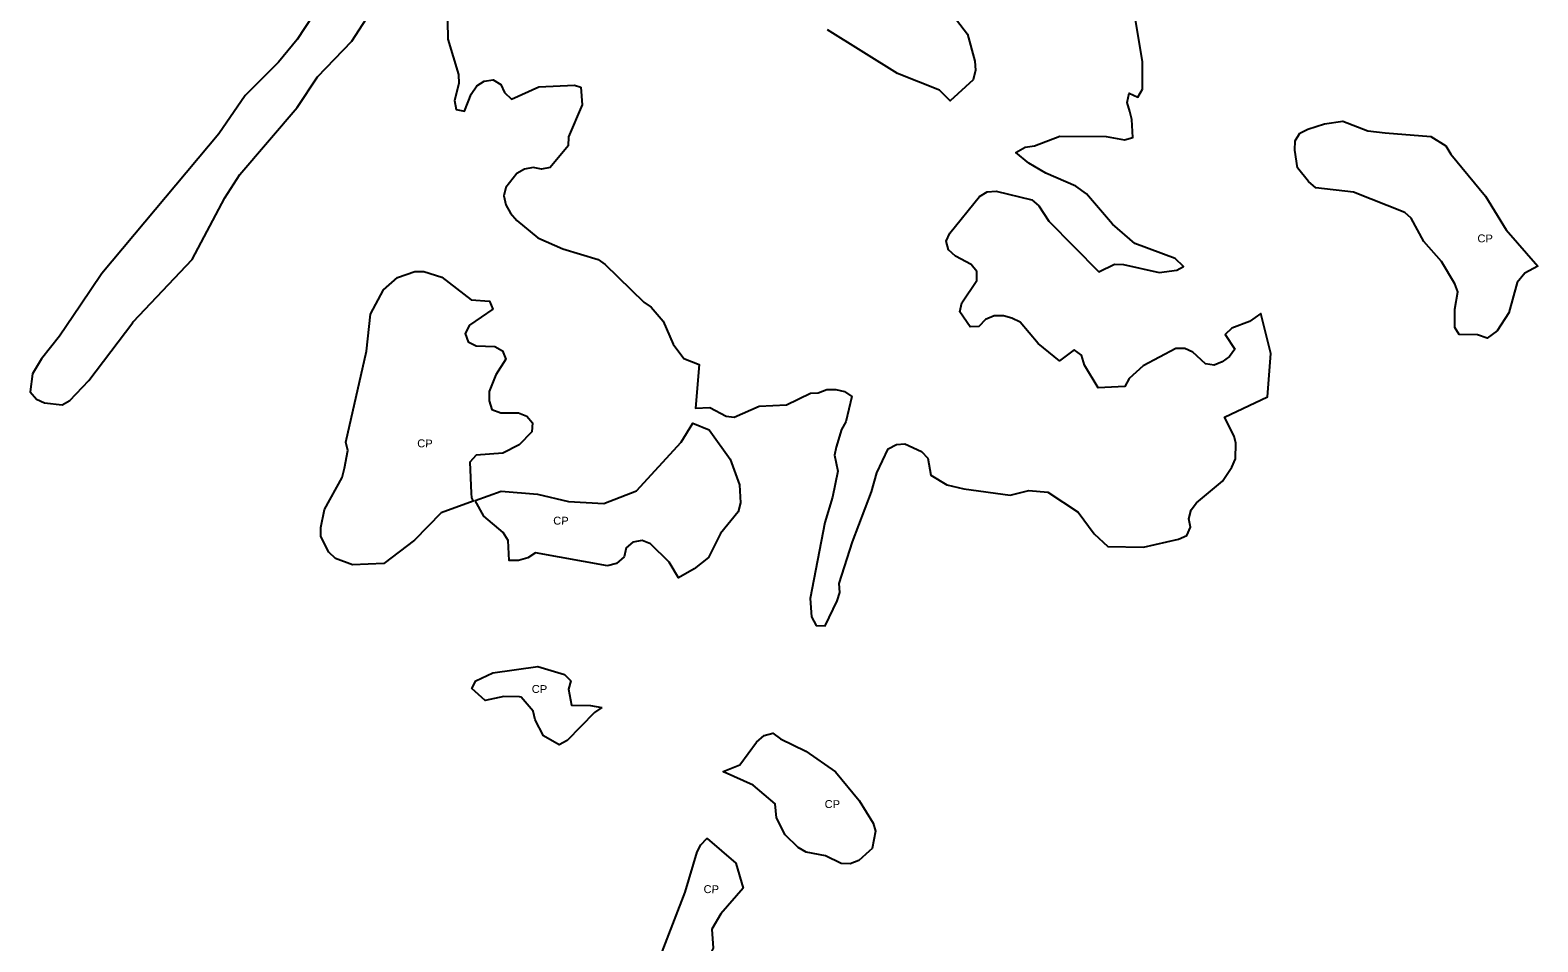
# Model space of a CAD drawing. Extents: x 713589 to 726391, y 7177764 to 7191819.
# Drawn here: x 719444 to 720662, y 7184376 to 7185112 of the extents above; entities that cross this region are included whole.
import ezdxf
from ezdxf.enums import TextEntityAlignment as Align

# ---------------------------------------------------------------- set-up
doc = ezdxf.new("R2010")
doc.units = 0
doc.header["$LTSCALE"] = 2.6
doc.layers.add('63', color=7, linetype='Continuous', lineweight=25)

msp = doc.modelspace()

# ---------------------------------------------------------------- linework, layer by layer
at = {"layer": '63'}
for points in [[(719684.37, 7185142.87), (719659.66, 7185104.86), (719644.45, 7185086.49), (719617.52, 7185059.57), (719596.29, 7185028.84), (719501.86, 7184915.77), (719484.61, 7184890.22), (719467.64, 7184865.09), (719453.07, 7184847.03), (719445.78, 7184834.68), (719443.87, 7184820.11), (719448.94, 7184814.4), (719455.59, 7184811.23), (719469.85, 7184809.65), (719475.87, 7184813.13), (719491.39, 7184829.28), (719526.84, 7184876.32), (719527.2, 7184876.8), (719574.73, 7184927.16), (719601.03, 7184976.89), (719613.39, 7184995.89), (719659.65, 7185050.06), (719676.13, 7185074.76), (719703.69, 7185103.59), (719754.07, 7185181.59)], [(720169.06, 7185151.34), (720201.05, 7185109.2), (720207.07, 7185087.34), (720207.7, 7185080.06), (720205.8, 7185072.45), (720187.14, 7185055.49), (720178.57, 7185064.09), (720144.49, 7185077.44), (720087.97, 7185112.76)], [(720369.39, 7184855.35), (720343.06, 7184841.2), (720331.87, 7184831), (720328.25, 7184824.46), (720306.67, 7184823.6), (720295.68, 7184841.87), (720293.37, 7184849.77), (720287.45, 7184854.05), (720275.6, 7184845.16), (720258.17, 7184859.32), (720243.69, 7184876.43), (720237.11, 7184879.72), (720230.2, 7184881.7), (720222.63, 7184881.7), (720215.72, 7184878.74), (720210.45, 7184873.15), (720203.21, 7184872.82), (720194.99, 7184885), (720196.64, 7184892.24), (720208.81, 7184910.33), (720208.82, 7184917.57), (720204.21, 7184923.17), (720191.38, 7184929.75), (720185.78, 7184935.02), (720183.81, 7184941.93), (720186.77, 7184948.51), (720210.8, 7184978.12), (720217.05, 7184981.74), (720224.29, 7184982.4), (720253.25, 7184975.48), (720258.84, 7184970.54), (720266.74, 7184958.04), (720307.21, 7184917.23), (720320.04, 7184923.48), (720327.28, 7184923.15), (720355.91, 7184916.56), (720370.39, 7184918.53), (720375.62, 7184921.6), (720369.05, 7184927.92), (720336.28, 7184940.02), (720318.19, 7184955.77), (720297.35, 7184980.27), (720288.68, 7184986.39), (720264.54, 7184996.83), (720250.63, 7185005.13), (720240.28, 7185013.58), (720247.66, 7185017.93), (720255.23, 7185018.92), (720275.64, 7185026.81), (720313.15, 7185026.48), (720327.96, 7185023.84), (720334.87, 7185025.81), (720333.88, 7185040.29), (720332.22, 7185046.64), (720330.27, 7185054.11), (720331.83, 7185061.47), (720338.76, 7185058.21), (720342.51, 7185064.84), (720342.51, 7185087.22), (720331.67, 7185151.72)], [(719781.06, 7185120.03), (719781.39, 7185105.22), (719789.94, 7185076.59), (719790.26, 7185069.35), (719786.64, 7185055.53), (719787.96, 7185048.29), (719794.87, 7185046.97), (719800.13, 7185060.79), (719804.74, 7185067.37), (719810.67, 7185071.32), (719817.91, 7185072.3), (719824.16, 7185068.68), (719827.12, 7185062.1), (719832.84, 7185056.74), (719854.89, 7185066.65), (719883.62, 7185068.07), (719888.77, 7185066.47)], [(719888.77, 7185066.47), (719889.97, 7185052.22), (719878.78, 7185026.22), (719878.45, 7185018.98), (719863.96, 7185001.55), (719857.05, 7185000.23), (719850.14, 7185001.55), (719843.23, 7185000.23), (719836.98, 7184996.61), (719828.09, 7184985.43), (719826.45, 7184978.52), (719828.09, 7184971.28), (719832.04, 7184964.7), (719836.97, 7184958.77), (719854.08, 7184944.62), (719874.15, 7184935.73), (719902.78, 7184927.17), (719908.46, 7184923.16), (719939.63, 7184892.61), (719945.55, 7184888.66), (719955.42, 7184877.47), (719963.32, 7184858.71), (719971.87, 7184847.19), (719984.38, 7184842.26), (719981.38, 7184807.07), (719992.99, 7184807.57), (720006.15, 7184800.66), (720012.73, 7184799.67), (720032.81, 7184808.55), (720054.86, 7184809.86), (720074.27, 7184819.07), (720080.53, 7184819.4), (720087.44, 7184822.03), (720094.68, 7184822.03), (720101.92, 7184820.38), (720107.84, 7184816.43), (720102.9, 7184796.03), (720099.28, 7184789.78), (720095, 7184775.63), (720093.68, 7184769.05), (720096.31, 7184756.22), (720092.03, 7184735.16), (720085.77, 7184714.75), (720073.92, 7184653.22), (720075.23, 7184638.41), (720078.85, 7184631.5), (720086.09, 7184631.17), (720095.96, 7184651.24), (720097.94, 7184658.15), (720097.61, 7184665.39), (720108.15, 7184698.95), (720123.62, 7184739.43), (720127.9, 7184754.89), (720137.12, 7184774.31), (720143.7, 7184777.6), (720150.61, 7184778.25), (720164.1, 7184772), (720169.04, 7184766.73), (720171.67, 7184752.91), (720184.5, 7184745.01), (720198.32, 7184741.72), (720235.5, 7184736.78), (720250.64, 7184740.39), (720266.11, 7184739.07), (720290.46, 7184722.94), (720303.62, 7184705.5), (720314.47, 7184695.3), (720343.43, 7184694.64), (720371.73, 7184701.21), (720378.32, 7184704.17), (720381.28, 7184710.75), (720379.96, 7184717.66), (720381.94, 7184724.9), (720386.22, 7184730.5), (720407.28, 7184747.93), (720414.85, 7184759.45), (720417.81, 7184766.03), (720417.82, 7184778.86), (720416.5, 7184784.46), (720408.81, 7184799.69), (720443.66, 7184816.13), (720443.92, 7184819.8), (720446.2, 7184851.29), (720438.15, 7184883.52), (720428.96, 7184877.06), (720414.81, 7184871.79), (720409.21, 7184866.53), (720417.11, 7184854.68), (720412.83, 7184848.76), (720406.9, 7184844.48), (720400.32, 7184841.85), (720393.41, 7184842.84), (720383.21, 7184852.39), (720376.63, 7184855.35), (720369.39, 7184855.35)]]:
    msp.add_lwpolyline(points, dxfattribs=at)
for points in [[(720469.53, 7185029.28), (720476.11, 7185032.57), (720489.6, 7185036.84), (720504.41, 7185038.82), (720524.48, 7185031.24), (720538.71, 7185029.5), (720575.49, 7185026.63), (720587.66, 7185019.06), (720591.61, 7185012.15), (720619.57, 7184978.25), (720636.35, 7184951.26), (720661.95, 7184921.68), (720651.43, 7184915.99), (720645.16, 7184908.57), (720638.62, 7184884.2), (720629.19, 7184869.63), (720621.06, 7184863.63), (720613.3, 7184866.36), (720598.49, 7184866.69), (720594.87, 7184872.29), (720594.88, 7184887.1), (720597.18, 7184900.92), (720594.88, 7184907.5), (720584.02, 7184925.6), (720569.88, 7184941.73), (720559.68, 7184960.49), (720554.41, 7184965.09), (720512.95, 7184981.56), (720482.68, 7184985.18), (720476.76, 7184990.12), (720467.87, 7185001.31), (720465.57, 7185015.46), (720465.9, 7185023.03)], [(719819.25, 7184856.96), (719825.5, 7184853.34), (719828.13, 7184846.76), (719820.23, 7184833.92), (719814.64, 7184820.43), (719814.64, 7184812.86), (719816.94, 7184805.95), (719824.18, 7184803.32), (719838.33, 7184803.32), (719845.24, 7184800.68), (719849.84, 7184795.09), (719849.18, 7184787.85), (719838.98, 7184777.32), (719825.82, 7184770.74), (719804.1, 7184769.1), (719799.16, 7184763.51), (719800.3, 7184738.32), (719800.47, 7184734.55), (719801.91, 7184731.84), (719775.85, 7184722.48), (719754.31, 7184700.3), (719729.59, 7184681.62), (719704.26, 7184680.36), (719690.55, 7184685.54), (719685.29, 7184690.8), (719678.71, 7184703.31), (719678.71, 7184710.55), (719681.68, 7184725.03), (719695.83, 7184751.02), (719697.81, 7184758.59), (719700.44, 7184772.74), (719698.8, 7184779.65), (719715.59, 7184853.03), (719718.89, 7184882.97), (719729.42, 7184902.72), (719740.61, 7184912.59), (719754.76, 7184917.52), (719762, 7184917.52), (719776.48, 7184912.91), (719800.17, 7184894.48), (719814.98, 7184893.49), (719817.61, 7184886.91), (719798.85, 7184874.07), (719795.23, 7184867.49), (719797.86, 7184860.58), (719804.11, 7184857.29)], [(719910.37, 7184679.57), (719852.13, 7184690.11), (719845.88, 7184686.17), (719838.31, 7184683.86), (719830.74, 7184683.87), (719830.08, 7184699.99), (719826.14, 7184706.57), (719810.34, 7184719.74), (719803.49, 7184732.41), (719824.32, 7184739.89), (719853.78, 7184737.67), (719878.81, 7184731.64), (719907.32, 7184730.06), (719933.62, 7184740.19), (719969.74, 7184779.46), (719979.27, 7184794.88), (719992.33, 7184789.47), (720009.44, 7184765.77), (720017, 7184745.04), (720017.66, 7184730.56), (720016.01, 7184723.32), (720001.53, 7184705.88), (719991.98, 7184686.47), (719980.46, 7184677.26), (719967.63, 7184670.02), (719960.06, 7184682.53), (719944.93, 7184697.34), (719938.35, 7184699.97), (719930.78, 7184698.66), (719925.51, 7184694.05), (719923.87, 7184686.81), (719917.61, 7184681.55)], [(719905.7, 7184565.12), (719899.82, 7184561.11), (719877.77, 7184538.41), (719871.19, 7184535.12), (719858.68, 7184542.36), (719851.78, 7184555.2), (719850.13, 7184562.11), (719840.51, 7184573.58), (719839.21, 7184573.86), (719826.67, 7184574.16), (719811.53, 7184570.85), (719800.77, 7184580.54), (719804.07, 7184586.8), (719817.56, 7184593.05), (719854.09, 7184598.3), (719875.48, 7184591.72), (719880.74, 7184586.78), (719878.76, 7184579.87), (719881.11, 7184566.95), (719896.71, 7184566.8)], [(720113.3, 7184441.42), (720106.39, 7184438.79), (720099.15, 7184439.12), (720086.32, 7184445.38), (720070.85, 7184448.34), (720064.27, 7184451.96), (720053.74, 7184462.17), (720046.84, 7184475.99), (720045.65, 7184487.44), (720028.06, 7184502.32), (720004.65, 7184512.81), (720003.68, 7184513.49), (720017.23, 7184518.77), (720030.72, 7184537.2), (720036.97, 7184542.46), (720043.89, 7184544.43), (720050.14, 7184539.83), (720070.54, 7184529.95), (720094.56, 7184513.16), (720113.64, 7184490.13), (720124.82, 7184471.7), (720126.8, 7184465.11), (720124.16, 7184451.29), (720121.59, 7184448.96)], [(719946.83, 7184269.55), (719939.92, 7184267.24), (719932.68, 7184267.9), (719926.1, 7184270.21), (719925.11, 7184277.12), (719941.24, 7184333.39), (719973.18, 7184415.98), (719982.73, 7184448.55), (719985.69, 7184454.15), (719990.63, 7184459.41), (719990.72, 7184459.43), (720013.99, 7184439.33), (720019.91, 7184419.26), (720001.8, 7184398.53), (719994.56, 7184386.03), (719995.55, 7184370.56), (719983.37, 7184345.88), (719977.44, 7184317.58), (719966.9, 7184291.26), (719962.63, 7184285.01)]]:
    msp.add_lwpolyline(points, close=True, dxfattribs=at)

# ---------------------------------------------------------------- texts
at = {"layer": '63', "width": 1.05}
for p in [(720619.32, 7184940.98), (719762.78, 7184775.35), (719872.66, 7184712.91), (719855.3, 7184576.88), (720091.92, 7184483.9), (719994.11, 7184415.13)]:
    msp.add_text('CP', height=6.4, rotation=359.062, dxfattribs=at).set_placement(p, align=Align.CENTER)

doc.saveas('drawing.dxf')
